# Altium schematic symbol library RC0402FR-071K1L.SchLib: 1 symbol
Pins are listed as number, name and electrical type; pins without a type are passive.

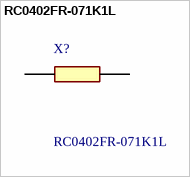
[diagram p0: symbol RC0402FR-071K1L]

## RC0402FR-071K1L
designator X?
RESISTOR, 0402 1.1K Ohms +/-1% 1/16 W; Manufacturer_Name: Yageo Group; Geometry.Height: 0.4mm
footprint RESC1005X40N
pins: 1, 2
